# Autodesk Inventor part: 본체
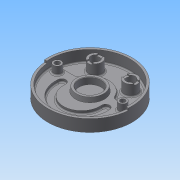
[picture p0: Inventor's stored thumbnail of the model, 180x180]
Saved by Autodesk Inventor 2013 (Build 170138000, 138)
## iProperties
Created: 2015-04
Part Number: 본체
Material: 일반
Document SubType Name: Modeling
Designer: Administrator
Density: 1 g/cm^3
Author: Administrator
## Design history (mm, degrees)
sketch "스케치1"
  geometry: C1 r 95 at (0, 0); 1 further point
  constraints: 1 centre point, 1 coincident
  dimensions: "d0" = 190 diameter of C1
extrude "돌출1" new body sketch "스케치1" distance "d2" = 32; taper "d3" = 0 deg
sketch "스케치2"
  geometry: C1 r 90 at (0, 0); 1 further point
  constraints: 1 centre point, 1 coincident
  dimensions: "d4" = 180 diameter of C1
extrude "돌출2" cut sketch "스케치2" distance "d6" = 25; taper "d7" = 0 deg
sketch "스케치6"
  geometry: L1 (-95, 0)-(-42, 0); L2 (42, 0)-(95, 0); A1 r 42 centre (0, 0) between (42, 0) and (-42, 0); A2 r 95 centre (0, 0) between (-95, 0) and (95, 0); 1 further point
  constraints: 4 end point, 4 point on circle, 2 centre point, 2 horizontal, 1 coincident
  dimensions: "d22" = 84 diameter of A1; "d25" = 190 diameter of A2
sketch "스케치7"
  geometry: C1 r 35 at (0, 0); 1 further point
  constraints: 1 centre point, 1 coincident
  dimensions: "d28" = 70 diameter of C1
extrude "돌출6" join sketch "스케치7" distance "d30" = 24; taper "d31" = -10 deg
sketch "스케치8"
  geometry: L1 (-94.239, 12)-(-40.249, 12); L2 (40.249, 12)-(94.239, 12); A1 r 42 centre (0, 0) between (40.249, 12) and (-40.249, 12); A2 r 95 centre (0, 0) between (-94.239, 12) and (94.239, 12); 1 further point
  constraints: 4 end point, 4 point on circle, 2 centre point, 2 coincident
  dimensions: "d34" = 84 diameter of A1; "d77" = 190 diameter of A2
extrude "돌출8" join sketch "스케치8" distance "d37" = 14; taper "d38" = 0 deg
fillet "모깎기1" dims "d39" = 10
sketch "스케치9"
  geometry: L1 (-58.788, -14)-(-58.741, -14); L2 (-40.741, -14)-(-40.694, -14); L3 (40.694, -14)-(40.808, -14.624); L4 (58.774, -13.838)-(58.774, -13.838); C1 r 95 at (0, 0) reference; A1 r 59 centre (0, -19) between (-58.788, -14) and (58.774, -13.838); A2 r 41 centre (0, -19) between (-40.694, -14) and (40.694, -14); A3 r 9 centre (-49.741, -14) between (-40.828, -15.251) and (-58.741, -14); A4 r 9 centre (49.808, -14.624) between (58.774, -13.838) and (40.843, -15.412); 2 further points
  constraints: 13 point on circle, 8 end point, 4 centre point, 1 coincident, 1 midpoint
  dimensions: "d41" = 118 diameter of A1; "d42" = 82 diameter of A2; "d44" = 18 diameter of A3; "d45" = 18 diameter of A4
extrude "돌출9" cut sketch "스케치9" distance "d46" = 7; taper "d47" = 0 deg
sketch "스케치10"
  geometry: L1 (-40, 52)-(40, 52); C1 r 95 at (0, 0) reference; C2 r 15 at (-40, 52); C3 r 15 at (40, 52); C4 r 10 at (-40, 52); C5 r 10 at (40, 52); 2 further points
  constraints: 4 centre point, 4 coincident, 2 end point, 1 midpoint, 1 vertical alignment
  dimensions: "d49" = 80 distance of L1.start L1.end; "d50" = 52 distance of point (0, 0) point (0, 52); "d51" = 30 diameter of C2; "d52" = 30 diameter of C3; "d53" = 20 diameter of C4; "d54" = 20 diameter of C5
extrude "돌출10" join sketch "스케치10" distance "d55" = 32; taper "d56" = 0 deg
sketch "스케치11"
  geometry: C1 r 10 at (-40, 52) reference; C2 r 10 at (40, 52) reference; C3 r 10 at (-40, 52); C4 r 10 at (40, 52); 1 further point
  constraints: 2 centre point, 2 coincident, 2 concentric
extrude "돌출12" cut sketch "스케치11" distance "d59" = 32; taper "d60" = 0 deg
sketch "스케치12"
  geometry: L1 (-74, 0)-(74, 0); 2 further points
  constraints: 2 coincident, 2 end point, 1 midpoint
  dimensions: "d61" = 148 distance of L1.start L1.end
hole "구멍1" sketch "스케치12" at (-74, 0), (74, 0) diameter "d63" = 11; stored, may be unused: countersink angle "d67" = 90 deg, drill point angle "d69" = 118 deg; dims "d64" = 6, "d65" = 18, "d66" = 11, "d68" = 8
node "작업 평면1"
node "작업 평면2"
sketch "스케치14"
  geometry: C1 r 9 at (-74, 0) reference; C2 r 9 at (74, 0) reference; C3 r 9 at (-74, 0); C4 r 9 at (74, 0); C5 r 5.5 at (-74, 0); C6 r 5.5 at (74, 0); 1 further point
  constraints: 5 coincident, 4 centre point, 2 concentric
  dimensions: "d79" = 11 diameter of C6; "d81" = 11 diameter of C5
extrude "돌출14" join sketch "스케치14" distance "d82" = 21; taper "d83" = 0 deg
sketch "스케치16"
  geometry: C1 r 15 at (0, 0) reference; 1 further point
sketch "스케치17"
  geometry: L1 (-6, 21.271)-(6, 21.271); L2 (-6, 21.271)-(-6, -22); L3 (-6, -22)-(6, -22); L4 (6, -22)-(6, 21.271); C1 r 15 at (0, 0) reference; 2 further points
  constraints: 8 end point, 3 perpendicular, 1 horizontal, 1 midpoint, 1 vertical alignment
  dimensions: "d84" = 12 distance of L1.start L1.end
extrude "돌출15" cut sketch "스케치17" distance "d86" = 3; taper "d87" = 0 deg
sketch "스케치18"
  geometry: L1 (-22.5, 6)-(22.5, 6); L2 (22.5, 6)-(22.5, -6); L3 (22.5, -6)-(-22.5, -6); L4 (-22.5, -6)-(-22.5, 6); L5 (-22.5, 6)-(22.5, -6); L6 (22.5, 6)-(-22.5, -6); C1 r 10 at (0, 0) reference; 3 further points
  constraints: 12 end point, 3 midpoint, 2 parallel, 1 coincident, 1 horizontal, 1 perpendicular
  dimensions: "d88" = 12 distance of L1.end L2.end
extrude "돌출16" cut sketch "스케치18" distance "d90" = 3; taper "d91" = 0 deg
sketch "스케치19"
  geometry: C1 r 25 at (0, 0); 1 further point
  constraints: 1 centre point, 1 coincident
  dimensions: "d92" = 50 diameter of C1
extrude "돌출17" cut sketch "스케치19" distance "d94" = 15; taper "d95" = 0 deg
chamfer "모따기1" distance "d96" = 1; stored, may be unused: second distance "d97" = 2, angle "d98" = 45 deg
fillet "모깎기2" dims "d99" = 10
fillet "모깎기3" dims "d100" = 3
fillet "모깎기4" dims "d101" = 3
fillet "모깎기5" dims "d102" = 3
fillet "모깎기6" dims "d103" = 3
fillet "모깎기7" dims "d104" = 3
fillet "모깎기8" dims "d105" = 3
fillet "모깎기9" dims "d106" = 3
node "작업 평면3"
sketch "스케치22"
  geometry: L1 (89.658, -7.844)-(94.638, -8.28); L2 (-89.658, -7.844)-(-94.638, -8.28); A1 r 90 centre (0, 0) between (-89.658, -7.844) and (89.658, -7.844); A2 r 95 centre (0, 0) between (-94.638, -8.28) and (94.638, -8.28); 2 further points
  constraints: 4 end point, 4 point on circle, 2 centre point, 2 coincident
extrude "돌출18" cut sketch "스케치22" distance "d124" = 5; taper "d125" = 0 deg
node "솔리드1"
other parameters: "d40" = 19, "d43" = 5, "d70" = 0, "d76" = 12, "d78" = 11, "d107" = 92, "d110" = 148, "d113" = 5.5
